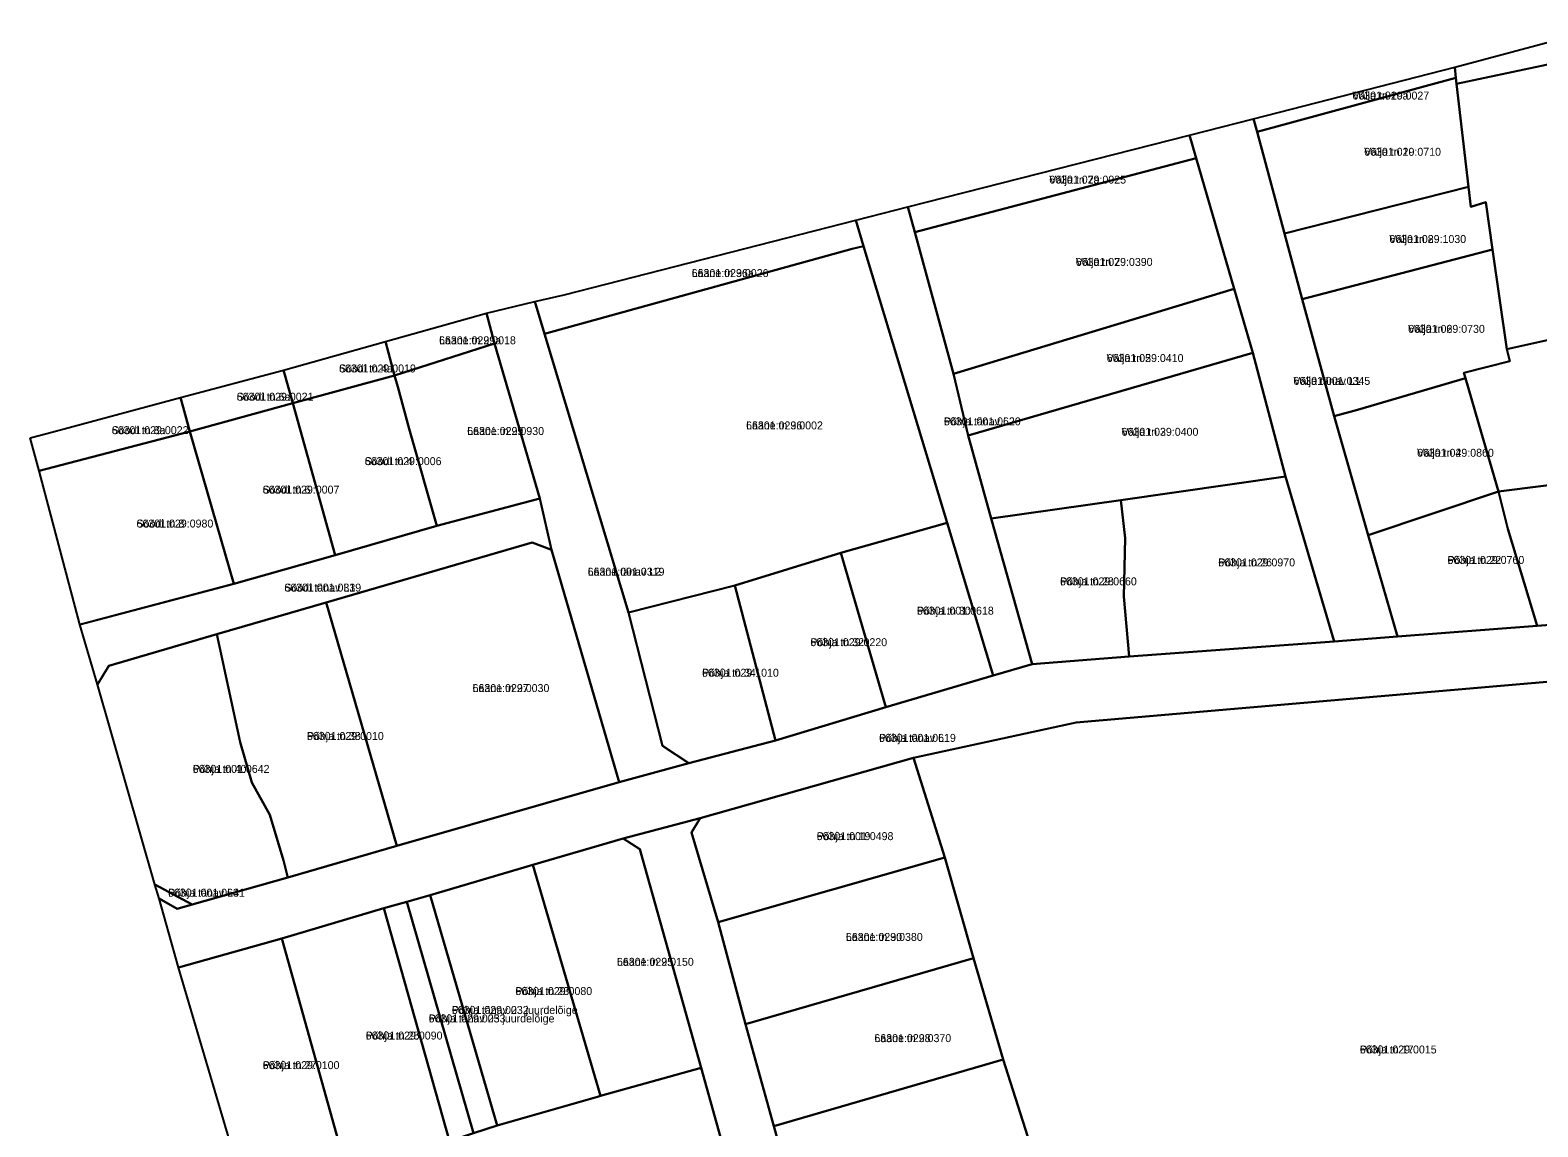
# Model space of a CAD drawing. Extents: x 632278 to 636344, y 6578401 to 6583362.
# Drawn here: x 632758.9 to 633043.6, y 6582376.8 to 6582584 of the extents above; entities that cross this region are included whole.
import ezdxf

# ---------------------------------------------------------------- set-up
doc = ezdxf.new("R2010")
doc.units = 0
for name, color, linetype in [('L_AADRESS', 7, 'Continuous'), ('PIIR', 7, 'Continuous'), ('TUNNUS', 7, 'Continuous')]:
    doc.layers.add(name, color=color, linetype=linetype)

msp = doc.modelspace()

# ---------------------------------------------------------------- linework, layer by layer
at = {"layer": 'PIIR'}
for points in [[(633054.06, 6582583.99), (633055, 6582579.52), (633028.22, 6582573.86), (633028.14, 6582574.96), (633027.95, 6582576.97)], [(633055, 6582579.52), (633064.4, 6582529.65), (633037.77, 6582523.74), (633035.07, 6582542.55), (633033.79, 6582551.5), (633030.98, 6582550.62), (633030.53, 6582554.4), (633028.22, 6582573.86)], [(633027.95, 6582576.97), (633028.14, 6582574.96), (632990.59, 6582564.79), (632989.95, 6582567.26)], [(632990.59, 6582564.79), (633028.14, 6582574.96), (633028.22, 6582573.86), (633030.53, 6582554.4), (632995.76, 6582545.55)], [(632977.85, 6582564.17), (632989.95, 6582567.26), (632990.59, 6582564.79), (632995.76, 6582545.55), (632999.14, 6582533.16), (633005.15, 6582511.07), (633011.6, 6582488.58), (633017.08, 6582469.47), (633005.17, 6582468.49), (632995.99, 6582499.68), (632989.78, 6582523), (632986.28, 6582535.15), (632979.12, 6582559.83)], [(632924.66, 6582550.59), (632977.85, 6582564.17), (632979.12, 6582559.83), (632925.97, 6582545.83)], [(632925.97, 6582545.83), (632979.12, 6582559.83), (632986.28, 6582535.15), (632933.29, 6582519.08)], [(632995.76, 6582545.55), (633030.53, 6582554.4), (633030.98, 6582550.62), (633033.79, 6582551.5), (633035.07, 6582542.55), (632999.14, 6582533.16)], [(632916.31, 6582543.19), (632914.83, 6582548.08), (632924.66, 6582550.59), (632925.97, 6582545.83), (632933.29, 6582519.08), (632936.08, 6582507.42), (632940.37, 6582491.71), (632948.11, 6582464.21), (632940.78, 6582462.09), (632932.07, 6582490.93)], [(632854.23, 6582532.7), (632859.75, 6582534.01), (632914.83, 6582548.08), (632916.31, 6582543.19), (632914.18, 6582542.69), (632856.06, 6582526.62)], [(632856.06, 6582526.62), (632914.18, 6582542.69), (632916.31, 6582543.19), (632932.07, 6582490.93), (632911.98, 6582485.23), (632892.01, 6582479.1), (632871.9, 6582473.95)], [(633005.15, 6582511.07), (632999.14, 6582533.16), (633035.07, 6582542.55), (633037.77, 6582523.74), (633038.34, 6582521.43), (633029.66, 6582519.28), (633029.96, 6582518.22), (633009.59, 6582512.26)], [(632933.29, 6582519.08), (632986.28, 6582535.15), (632989.78, 6582523), (632936.08, 6582507.42)], [(632826.07, 6582525.14), (632845.13, 6582530.53), (632846.59, 6582524.81), (632827.76, 6582518.77)], [(632845.13, 6582530.53), (632854.23, 6582532.7), (632856.06, 6582526.62), (632871.9, 6582473.95), (632878.33, 6582448.76), (632883.29, 6582445.54), (632870.13, 6582441.93), (632857.41, 6582485.79), (632855.19, 6582495.49), (632846.59, 6582524.81)], [(633032.91, 6582508.05), (633029.96, 6582518.22), (633029.66, 6582519.28), (633038.34, 6582521.43), (633037.77, 6582523.74), (633064.4, 6582529.65), (633070.7, 6582501.2), (633036.15, 6582496.82)], [(632806.8, 6582519.77), (632826.07, 6582525.14), (632827.76, 6582518.77), (632808.53, 6582513.51)], [(632835.72, 6582490.32), (632830.54, 6582508.65), (632828.36, 6582516.59), (632827.76, 6582518.77), (632846.59, 6582524.81), (632855.19, 6582495.49)], [(632936.08, 6582507.42), (632989.78, 6582523), (632995.99, 6582499.68), (632964.89, 6582495.22), (632940.37, 6582491.71)], [(632787.32, 6582514.59), (632806.8, 6582519.77), (632808.53, 6582513.51), (632789.12, 6582508.2)], [(632816.56, 6582484.82), (632808.53, 6582513.51), (632827.76, 6582518.77), (632828.36, 6582516.59), (632830.54, 6582508.65), (632835.72, 6582490.32)], [(633005.15, 6582511.07), (633009.59, 6582512.26), (633029.96, 6582518.22), (633032.91, 6582508.05), (633036.15, 6582496.82), (633011.6, 6582488.58)], [(632758.95, 6582506.96), (632762.1, 6582507.8), (632787.32, 6582514.59), (632789.12, 6582508.2), (632760.67, 6582500.75)], [(632789.12, 6582508.2), (632808.53, 6582513.51), (632816.56, 6582484.82), (632797.38, 6582479.37)], [(632760.67, 6582500.75), (632789.12, 6582508.2), (632797.38, 6582479.37), (632771.05, 6582472.4), (632768.36, 6582471.69)], [(632965.67, 6582488.01), (632964.89, 6582495.22), (632995.99, 6582499.68), (633005.17, 6582468.49), (632966.42, 6582465.69), (632965.42, 6582477.01)], [(633037.94, 6582489.81), (633036.15, 6582496.82), (633070.7, 6582501.2), (633073.38, 6582473.76), (633043.47, 6582471.48)], [(633036.15, 6582496.82), (633037.94, 6582489.81), (633043.47, 6582471.48), (633017.08, 6582469.47), (633011.6, 6582488.58)], [(632768.36, 6582471.69), (632797.38, 6582479.37), (632816.56, 6582484.82), (632835.72, 6582490.32), (632855.19, 6582495.49), (632857.41, 6582485.79), (632853.73, 6582487.18), (632814.82, 6582475.86), (632794.2, 6582469.86), (632773.83, 6582463.91), (632771.66, 6582460.37)], [(632940.37, 6582491.71), (632964.89, 6582495.22), (632965.67, 6582488.01), (632965.42, 6582477.01), (632966.42, 6582465.69), (632948.11, 6582464.21)], [(632920.5, 6582456.07), (632911.98, 6582485.23), (632932.07, 6582490.93), (632940.78, 6582462.09)], [(632814.82, 6582475.86), (632853.73, 6582487.18), (632857.41, 6582485.79), (632870.13, 6582441.93), (632828.21, 6582429.91)], [(632899.7, 6582449.78), (632892.01, 6582479.1), (632911.98, 6582485.23), (632920.5, 6582456.07)], [(632878.33, 6582448.76), (632871.9, 6582473.95), (632892.01, 6582479.1), (632899.7, 6582449.78), (632883.29, 6582445.54)], [(632828.21, 6582429.91), (632807.63, 6582423.94), (632806.79, 6582427.15), (632804.21, 6582435.75), (632800.81, 6582441.84), (632798.57, 6582449.46), (632794.2, 6582469.86), (632814.82, 6582475.86)], [(632789.57, 6582418.81), (632782.5, 6582422.57), (632771.66, 6582460.37), (632773.83, 6582463.91), (632794.2, 6582469.86), (632798.57, 6582449.46), (632800.81, 6582441.84), (632804.21, 6582435.75), (632806.79, 6582427.15), (632807.63, 6582423.94)], [(633075.2, 6582463.43), (633077.8, 6582386.33), (633070.2, 6582386.4), (633070.38, 6582382.02), (633077.94, 6582382.05), (633079.64, 6582336.91), (633056.87, 6582334.44), (633034.63, 6582329.54), (633012.24, 6582325.89), (633012.31, 6582326.81), (632990.17, 6582322.14), (632962.98, 6582317.93), (632958.95, 6582332.08), (632953.33, 6582351.51), (632948.72, 6582370.57), (632942.69, 6582389.52), (632937.03, 6582408.7), (632931.66, 6582427.68), (632925.7, 6582446.5), (632956.46, 6582453.19)], [(632883.82, 6582432.43), (632885.46, 6582435.14), (632925.7, 6582446.5), (632931.66, 6582427.68), (632888.88, 6582415.45)], [(632853.85, 6582426.34), (632870.93, 6582431.28), (632874.09, 6582429.24), (632885.63, 6582387.98), (632866.64, 6582382.67)], [(632834.48, 6582420.6), (632853.85, 6582426.34), (632866.64, 6582382.67), (632866.05, 6582382.47), (632847.1, 6582377.07)], [(632888.88, 6582415.45), (632931.66, 6582427.68), (632937.03, 6582408.7), (632894.04, 6582396.2)], [(632783.28, 6582419.96), (632782.5, 6582422.57), (632789.57, 6582418.81), (632786.71, 6582418.02)], [(632825.72, 6582418.14), (632830.04, 6582419.35), (632842.66, 6582375.6), (632838.14, 6582374.11)], [(632834.48, 6582420.6), (632847.1, 6582377.07), (632842.66, 6582375.6), (632830.04, 6582419.35)], [(632806.48, 6582412.41), (632825.72, 6582418.14), (632838.13, 6582374.11), (632818.75, 6582368.45)], [(632786.95, 6582406.91), (632806.48, 6582412.41), (632818.75, 6582368.45), (632800.56, 6582363.41), (632799.87, 6582363.22)], [(632894.04, 6582396.2), (632937.03, 6582408.7), (632942.69, 6582389.52), (632899.39, 6582376.93)], [(632800.56, 6582363.41), (632818.75, 6582368.45), (632838.13, 6582374.11), (632842.66, 6582375.6), (632847.1, 6582377.07), (632866.05, 6582382.47), (632866.64, 6582382.67), (632885.63, 6582387.98), (632891.4, 6582367.16), (632845.82, 6582354.06), (632805.79, 6582342.47)], [(632942.69, 6582389.52), (632948.72, 6582370.57), (632933.57, 6582366.11), (632904.77, 6582357.74), (632899.39, 6582376.93)]]:
    msp.add_lwpolyline(points, close=True, dxfattribs=at)
for points in [[(633075.2, 6582463.43), (632956.46, 6582453.19), (632925.7, 6582446.5), (632885.46, 6582435.14), (632870.93, 6582431.28), (632853.85, 6582426.34), (632834.48, 6582420.6), (632830.04, 6582419.35), (632825.72, 6582418.14), (632806.48, 6582412.41), (632786.95, 6582406.91), (632783.28, 6582419.96), (632786.71, 6582418.02), (632789.57, 6582418.81), (632807.63, 6582423.94), (632828.21, 6582429.91), (632870.13, 6582441.93), (632883.29, 6582445.54), (632899.7, 6582449.78), (632920.5, 6582456.07), (632940.78, 6582462.09), (632948.11, 6582464.21), (632966.42, 6582465.69), (633005.17, 6582468.49), (633017.08, 6582469.47), (633043.47, 6582471.48), (633073.38, 6582473.76)], [(632891.4, 6582367.16), (632885.63, 6582387.98), (632874.09, 6582429.24), (632870.93, 6582431.28), (632885.46, 6582435.14), (632883.82, 6582432.43), (632888.88, 6582415.45), (632894.04, 6582396.2), (632899.39, 6582376.93), (632904.77, 6582357.74)]]:
    msp.add_lwpolyline(points, dxfattribs=at)

# ---------------------------------------------------------------- texts
at = {"layer": 'L_AADRESS'}
for s, p in [('Välja tn 10a', (633008.6, 6582570.88)), ('Välja tn 10', (633010.82, 6582560.26)), ('Välja tn 7a', (632951.36, 6582555)), ('Välja tn 8', (633015.57, 6582543.78)), ('Lääne tn 36a', (632883.85, 6582537.35)), ('Välja tn 7', (632956.37, 6582539.45)), ('Välja tn 6', (633019.1, 6582526.81)), ('Lääne tn 29a', (632836.15, 6582524.65)), ('Välja tn 5', (632962.21, 6582521.29)), ('Söödi tn 4a', (632817.27, 6582519.33)), ('Välja tänav L1', (632997.46, 6582516.98)), ('Söödi tn 6a', (632797.94, 6582513.99)), ('Põhja tänav L2', (632931.47, 6582509.33)), ('Söödi tn 8a', (632774.35, 6582507.67)), ('Lääne tn 29', (632841.47, 6582507.51)), ('Lääne tn 36', (632894.12, 6582508.57)), ('Välja tn 3', (632965.02, 6582507.36)), ('Välja tn 4', (633020.8, 6582503.4)), ('Söödi tn 4', (632822.12, 6582501.82)), ('Söödi tn 6', (632802.84, 6582496.44)), ('Söödi tn 8', (632779.03, 6582490.03)), ('Lääne tänav L2', (632864.21, 6582480.93)), ('Põhja tn 26', (632983.27, 6582482.69)), ('Põhja tn 22', (633026.55, 6582483.15)), ('Söödi tänav L1', (632806.94, 6582477.93)), ('Põhja tn 28', (632953.39, 6582479.11)), ('Põhja tn 30', (632926.38, 6582473.57)), ('Põhja tn 32', (632906.25, 6582467.62)), ('Põhja tn 34', (632885.8, 6582461.85)), ('Lääne tn 27', (632842.48, 6582458.95)), ('Põhja tn 38', (632811.21, 6582449.89)), ('Põhja tänav L1', (632919.22, 6582449.54)), ('Põhja tn 40', (632789.64, 6582443.68)), ('Põhja tn 19', (632907.44, 6582430.98)), ('Põhja tänav L3', (632784.98, 6582420.29)), ('Lääne tn 30', (632912.97, 6582411.94)), ('Lääne tn 25', (632869.74, 6582407.24)), ('Põhja tn 23', (632850.56, 6582401.71)), ('Põhja tänav 23 juurdelõige', (632838.57, 6582398.14)), ('Põhja tänav 25 juurdelõige', (632834.19, 6582396.54)), ('Põhja tn 25', (632822.3, 6582393.31)), ('Lääne tn 28', (632918.35, 6582392.82)), ('Põhja tn 17', (633010, 6582390.68)), ('Põhja tn 27', (632802.85, 6582387.72))]:
    msp.add_text(s, height=1.5, dxfattribs=at).set_placement(p)
at = {"layer": 'TUNNUS'}
for s, p in [('66301:029:0027', (633008.6, 6582570.88)), ('66301:029:0710', (633010.82, 6582560.26)), ('66301:029:0025', (632951.36, 6582555)), ('66301:029:1030', (633015.57, 6582543.78)), ('66301:029:0026', (632883.85, 6582537.35)), ('66301:029:0390', (632956.37, 6582539.45)), ('66301:029:0730', (633019.1, 6582526.81)), ('66301:029:0018', (632836.15, 6582524.65)), ('66301:029:0410', (632962.21, 6582521.29)), ('66301:029:0019', (632817.27, 6582519.33)), ('66301:001:0345', (632997.46, 6582516.98)), ('66301:029:0021', (632797.94, 6582513.99)), ('66301:001:0620', (632931.47, 6582509.33)), ('66301:029:0022', (632774.35, 6582507.67)), ('66301:029:0930', (632841.47, 6582507.51)), ('66301:029:0002', (632894.12, 6582508.57)), ('66301:029:0400', (632965.02, 6582507.36)), ('66301:029:0860', (633020.8, 6582503.4)), ('66301:029:0006', (632822.12, 6582501.82)), ('66301:029:0007', (632802.84, 6582496.44)), ('66301:029:0980', (632779.03, 6582490.03)), ('66301:001:0319', (632864.21, 6582480.93)), ('66301:029:0970', (632983.27, 6582482.69)), ('66301:029:0760', (633026.55, 6582483.15)), ('66301:001:0339', (632806.94, 6582477.93)), ('66301:029:0660', (632953.39, 6582479.11)), ('66301:001:0618', (632926.38, 6582473.57)), ('66301:029:0220', (632906.25, 6582467.62)), ('66301:029:1010', (632885.8, 6582461.85)), ('66301:029:0030', (632842.48, 6582458.95)), ('66301:029:0010', (632811.21, 6582449.89)), ('66301:001:0619', (632919.22, 6582449.54)), ('66301:001:0642', (632789.64, 6582443.68)), ('66301:001:0498', (632907.44, 6582430.98)), ('66301:001:0641', (632784.98, 6582420.29)), ('66301:029:0380', (632912.97, 6582411.94)), ('66301:029:0150', (632869.74, 6582407.24)), ('66301:029:0080', (632850.56, 6582401.71)), ('66301:029:0032', (632838.57, 6582398.14)), ('66301:029:0033', (632834.19, 6582396.54)), ('66301:029:0090', (632822.3, 6582393.31)), ('66301:029:0370', (632918.35, 6582392.82)), ('66301:029:0015', (633010, 6582390.68)), ('66301:029:0100', (632802.85, 6582387.72))]:
    msp.add_text(s, height=1.5, dxfattribs=at).set_placement(p)

doc.saveas('drawing.dxf')
